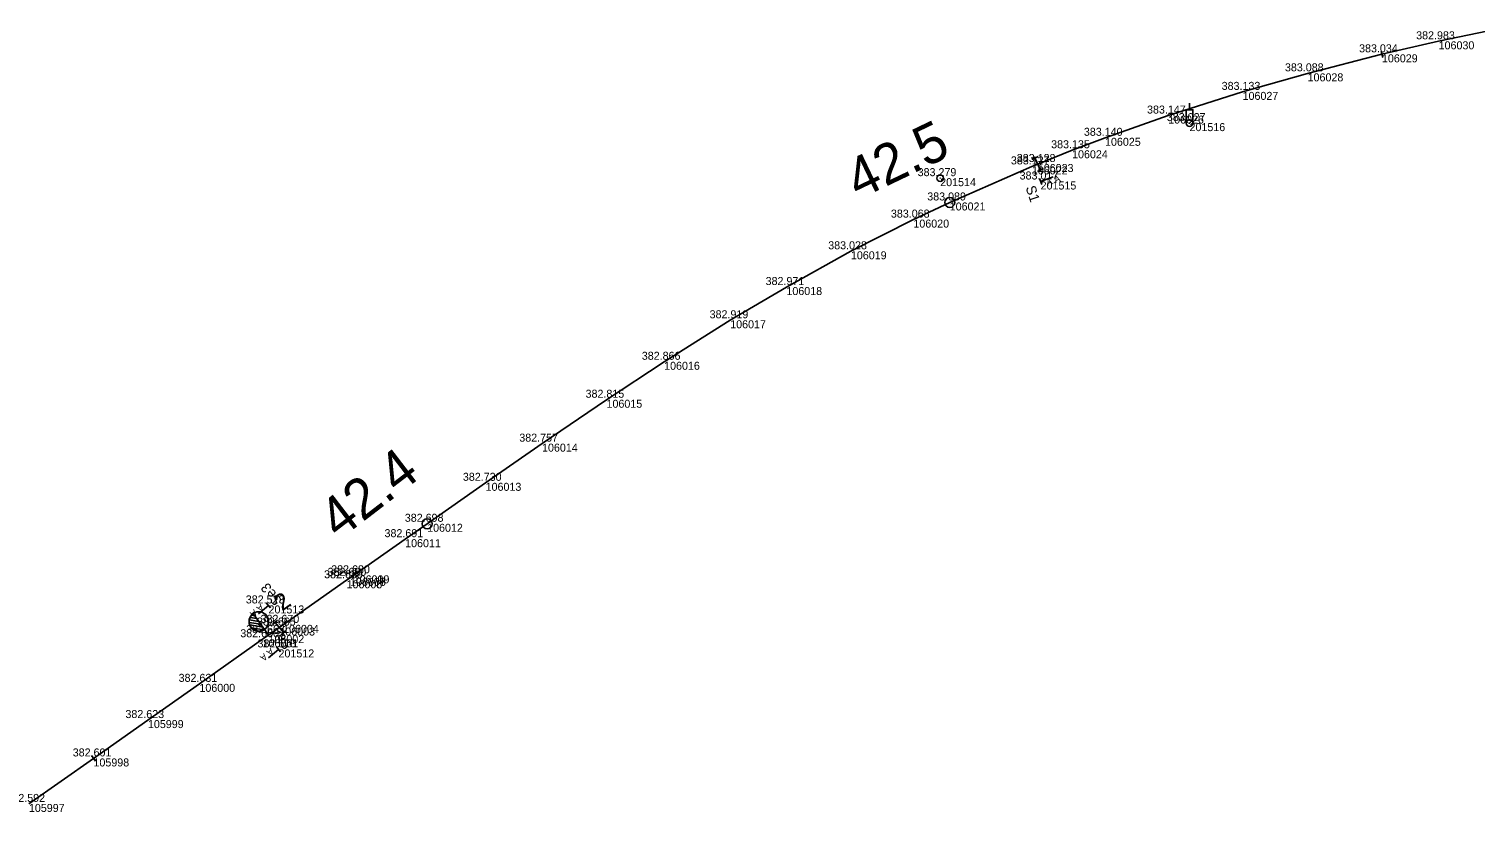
# Model space of a CAD drawing. Extents: x -514522 to -512811, y -1144589 to -1143575.
# Drawn here: x -513451.6 to -513234.8, y -1143710.1 to -1143592.8 of the extents above; entities that cross this region are included whole.
import ezdxf

# ---------------------------------------------------------------- set-up
doc = ezdxf.new("R2010")
doc.units = 0
for name, color, linetype in [('Vrstva 1', 7, 'Continuous'), ('Vrstva 2', 7, 'Continuous'), ('Vrstva 3', 7, 'Continuous'), ('Vrstva 4', 7, 'Continuous'), ('Vrstva 50', 7, 'Continuous'), ('Vrstva 6', 7, 'Continuous'), ('Vrstva 60', 7, 'Continuous'), ('Vrstva 61', 7, 'Continuous'), ('Vrstva 7', 7, 'Continuous')]:
    doc.layers.add(name, color=color, linetype=linetype)

msp = doc.modelspace()

# ---------------------------------------------------------------- linework, layer by layer
at = {"layer": 'Vrstva 1'}
for p, q in [((-513240.22, -1143594.63), (-513231.3, -1143592.78)), ((-513259.87, -1143599.43), (-513248.72, -1143596.58)), ((-513248.72, -1143596.58), (-513240.22, -1143594.63)), ((-513269.62, -1143602.21), (-513259.87, -1143599.43)), ((-513280.78, -1143605.76), (-513269.62, -1143602.21)), ((-513290.25, -1143609.09), (-513280.78, -1143605.76)), ((-513295.19, -1143610.96), (-513290.25, -1143609.09)), ((-513300.33, -1143613.02), (-513295.19, -1143610.96)), ((-513313.54, -1143618.78), (-513301.22, -1143613.38)), ((-513301.22, -1143613.38), (-513300.33, -1143613.02)), ((-513318.99, -1143621.35), (-513313.54, -1143618.78)), ((-513328.36, -1143626.1), (-513318.99, -1143621.35)), ((-513338.03, -1143631.46), (-513328.36, -1143626.1)), ((-513346.46, -1143636.44), (-513338.03, -1143631.46)), ((-513356.37, -1143642.66), (-513346.46, -1143636.44)), ((-513365.01, -1143648.35), (-513356.37, -1143642.66)), ((-513374.68, -1143654.93), (-513365.01, -1143648.35)), ((-513383.14, -1143660.8), (-513374.68, -1143654.93)), ((-513391.91, -1143666.94), (-513383.14, -1143660.8)), ((-513395.21, -1143669.25), (-513391.91, -1143666.94)), ((-513402.93, -1143674.67), (-513395.21, -1143669.25)), ((-513403.47, -1143675.04), (-513402.93, -1143674.67)), ((-513413.51, -1143682.09), (-513404, -1143675.41)), ((-513404, -1143675.41), (-513403.47, -1143675.04)), ((-513415.7, -1143683.62), (-513414.08, -1143682.49)), ((-513414.08, -1143682.49), (-513413.51, -1143682.09)), ((-513426.06, -1143690.93), (-513416.59, -1143684.25)), ((-513416.59, -1143684.25), (-513415.7, -1143683.62)), ((-513433.78, -1143696.36), (-513426.06, -1143690.93)), ((-513441.95, -1143702.11), (-513433.78, -1143696.36)), ((-513451.63, -1143708.93), (-513441.95, -1143702.11))]:
    msp.add_line(p, q, dxfattribs=at)
at = {"layer": 'Vrstva 2'}
for p, q in [((-513248.61, -1143597.07), (-513248.84, -1143596.1)), ((-513417.47, -1143681.15), (-513418.47, -1143680.98)), ((-513417.78, -1143680.72), (-513418.25, -1143680.64)), ((-513416.3, -1143682.79), (-513418, -1143680.41)), ((-513418, -1143680.41), (-513416.3, -1143682.79)), ((-513416.85, -1143682.01), (-513418.6, -1143681.72)), ((-513417.16, -1143681.58), (-513418.59, -1143681.34)), ((-513416.54, -1143682.44), (-513418.51, -1143682.11)), ((-513416.39, -1143682.84), (-513418.27, -1143682.54)), ((-513416.3, -1143682.79), (-513415.7, -1143683.62)), ((-513416.3, -1143682.79), (-513416.3, -1143682.79)), ((-513441.67, -1143702.53), (-513442.23, -1143701.69))]:
    msp.add_line(p, q, dxfattribs=at)
msp.add_circle((-513417.15, -1143681.59), 1.46, dxfattribs=at)
msp.add_arc((-513417.15, -1143681.6), 1.46, 125.6292, 305.5901, dxfattribs=at)
at = {"layer": 'Vrstva 3'}
for p, q in [((-513301.21, -1143612.33), (-513300.3, -1143611.9)), ((-513300.76, -1143612.11), (-513299.91, -1143613.93)), ((-513300.36, -1143614.14), (-513299.46, -1143613.71)), ((-513415.11, -1143682.04), (-513414.34, -1143681.4)), ((-513414.72, -1143681.72), (-513413.44, -1143683.25)), ((-513413.82, -1143683.57), (-513413.05, -1143682.93))]:
    msp.add_line(p, q, dxfattribs=at)
at = {"layer": 'Vrstva 4'}
msp.add_line((-513295.19, -1143610.96), (-513290.25, -1143609.09), dxfattribs=at)
at = {"layer": 'Vrstva 50'}
for p, q in [((-513277.58, -1143603.89), (-513277.58, -1143604.89)), ((-513277.53, -1143606.89), (-513277.63, -1143606.89))]:
    msp.add_line(p, q, dxfattribs=at)
msp.add_lwpolyline([(-513278.09, -1143606.89), (-513278.08, -1143604.89), (-513277.07, -1143604.89), (-513277.07, -1143606.89)], dxfattribs=at)
msp.add_circle((-513277.58, -1143606.89), 0.506, dxfattribs=at)
at = {"layer": 'Vrstva 6'}
for p, q in [((-513300.08, -1143615.17), (-513299.74, -1143616.11)), ((-513298.05, -1143614.96), (-513299.91, -1143615.64)), ((-513415.38, -1143679.56), (-513416.03, -1143678.8)), ((-513417.22, -1143680.45), (-513415.7, -1143679.18)), ((-513413.88, -1143686.15), (-513414.52, -1143685.38)), ((-513415.72, -1143687.04), (-513414.2, -1143685.77))]:
    msp.add_line(p, q, dxfattribs=at)
at = {"layer": 'Vrstva 60'}
for p, q in [((-513248.72, -1143596.58), (-513248.72, -1143596.58)), ((-513240.22, -1143594.63), (-513240.22, -1143594.63)), ((-513259.87, -1143599.43), (-513259.87, -1143599.43)), ((-513269.62, -1143602.21), (-513269.62, -1143602.21)), ((-513280.78, -1143605.76), (-513280.78, -1143605.76)), ((-513277.58, -1143606.89), (-513277.58, -1143606.89)), ((-513290.25, -1143609.09), (-513290.25, -1143609.09)), ((-513295.19, -1143610.96), (-513295.19, -1143610.96)), ((-513301.22, -1143613.38), (-513301.22, -1143613.38)), ((-513300.33, -1143613.02), (-513300.33, -1143613.02)), ((-513314.97, -1143615.14), (-513314.97, -1143615.14)), ((-513299.91, -1143615.64), (-513299.91, -1143615.64)), ((-513313.54, -1143618.78), (-513313.54, -1143618.78)), ((-513318.99, -1143621.35), (-513318.99, -1143621.35)), ((-513328.36, -1143626.1), (-513328.36, -1143626.1)), ((-513338.03, -1143631.46), (-513338.03, -1143631.46)), ((-513346.46, -1143636.44), (-513346.46, -1143636.44)), ((-513356.37, -1143642.66), (-513356.37, -1143642.66)), ((-513365.01, -1143648.35), (-513365.01, -1143648.35)), ((-513374.68, -1143654.93), (-513374.68, -1143654.93)), ((-513383.14, -1143660.8), (-513383.14, -1143660.8)), ((-513391.91, -1143666.94), (-513391.91, -1143666.94)), ((-513395.21, -1143669.25), (-513395.21, -1143669.25)), ((-513402.93, -1143674.66), (-513402.93, -1143674.66)), ((-513402.93, -1143674.67), (-513402.93, -1143674.67)), ((-513404, -1143675.41), (-513404, -1143675.41)), ((-513403.99, -1143675.41), (-513403.99, -1143675.41)), ((-513403.47, -1143675.04), (-513403.47, -1143675.04)), ((-513403.47, -1143675.04), (-513403.47, -1143675.04)), ((-513415.7, -1143679.18), (-513415.7, -1143679.18)), ((-513414.08, -1143682.49), (-513414.08, -1143682.49)), ((-513413.51, -1143682.09), (-513413.51, -1143682.09)), ((-513416.59, -1143684.25), (-513416.59, -1143684.25)), ((-513415.7, -1143683.62), (-513415.7, -1143683.62)), ((-513414.2, -1143685.77), (-513414.2, -1143685.77)), ((-513426.06, -1143690.93), (-513426.06, -1143690.93)), ((-513433.78, -1143696.36), (-513433.78, -1143696.36)), ((-513441.95, -1143702.11), (-513441.95, -1143702.11)), ((-513451.63, -1143708.93), (-513451.63, -1143708.93))]:
    msp.add_line(p, q, dxfattribs=at)
at = {"layer": 'Vrstva 7'}
msp.add_line((-513315.02, -1143615.14), (-513314.92, -1143615.14), dxfattribs=at)
for centre, radius in [((-513314.97, -1143615.14), 0.5), ((-513313.54, -1143618.78), 0.75), ((-513391.91, -1143666.94), 0.75)]:
    msp.add_circle(centre, radius, dxfattribs=at)

# ---------------------------------------------------------------- texts
at = {"layer": 'Vrstva 2'}
msp.add_text('2', height=2.5, rotation=35.5807, dxfattribs=at).set_placement((-513413.65, -1143680.12))
at = {"layer": 'Vrstva 6'}
for s, height, rotation, p in [('  A A ', 1, 20, (-513299.57, -1143616.58)), ('S1', 1.5, 288.4684, (-513302.18, -1143616.55)), ('Se3', 1.5, 128.4684, (-513413.59, -1143678.46)), ('  A A ', 1, 220, (-513416.35, -1143678.41)), ('Se4', 1.5, 128.4684, (-513412.09, -1143685.05)), ('  A A ', 1, 220, (-513414.85, -1143685))]:
    msp.add_text(s, height=height, rotation=rotation, dxfattribs=at).set_placement(p)
at = {"layer": 'Vrstva 60'}
for s, p in [('106029', (-513248.72, -1143597.78)), ('106030', (-513240.22, -1143595.83)), ('106028', (-513259.87, -1143600.63)), ('106027', (-513269.62, -1143603.41)), ('106026', (-513280.78, -1143606.96)), ('201516', (-513277.58, -1143608.09)), ('106025', (-513290.25, -1143610.29)), ('106024', (-513295.19, -1143612.16)), ('106022', (-513301.22, -1143614.58)), ('106023', (-513300.33, -1143614.22)), ('201514', (-513314.97, -1143616.34)), ('201515', (-513299.91, -1143616.84)), ('106021', (-513313.54, -1143619.98)), ('106020', (-513318.99, -1143622.55)), ('106019', (-513328.36, -1143627.3)), ('106018', (-513338.03, -1143632.66)), ('106017', (-513346.46, -1143637.64)), ('106016', (-513356.37, -1143643.86)), ('106015', (-513365.01, -1143649.55)), ('106014', (-513374.68, -1143656.13)), ('106013', (-513383.14, -1143662)), ('106012', (-513391.91, -1143668.14)), ('106011', (-513395.21, -1143670.45)), ('106010', (-513402.93, -1143675.86)), ('106009', (-513402.93, -1143675.87)), ('106006', (-513403.99, -1143676.61)), ('106005', (-513404, -1143676.61)), ('106008', (-513403.47, -1143676.24)), ('106007', (-513403.47, -1143676.24)), ('201513', (-513415.7, -1143680.38)), ('106003', (-513414.08, -1143683.69)), ('106004', (-513413.51, -1143683.29)), ('106001', (-513416.59, -1143685.45)), ('106002', (-513415.7, -1143684.82)), ('201512', (-513414.2, -1143686.97)), ('106000', (-513426.06, -1143692.13)), ('105999', (-513433.78, -1143697.56)), ('105998', (-513441.95, -1143703.31)), ('105997', (-513451.63, -1143710.13))]:
    msp.add_text(s, height=1.2, dxfattribs=at).set_placement(p)
at = {"layer": 'Vrstva 61'}
for s, p in [('382.983', (-513243.59, -1143594.33)), ('383.034', (-513252.15, -1143596.28)), ('383.088', (-513263.27, -1143599.13)), ('383.133', (-513272.76, -1143601.91)), ('383.147', (-513283.95, -1143605.46)), ('383.027', (-513280.98, -1143606.59)), ('383.135', (-513298.33, -1143610.66)), ('383.140', (-513293.42, -1143608.79)), ('383.128', (-513303.48, -1143612.72)), ('383.279', (-513318.35, -1143614.84)), ('383.127', (-513304.37, -1143613.08)), ('383.017', (-513303.06, -1143615.34)), ('383.089', (-513316.91, -1143618.48)), ('383.068', (-513322.36, -1143621.05)), ('383.028', (-513331.76, -1143625.8)), ('382.971', (-513341.15, -1143631.16)), ('382.919', (-513349.55, -1143636.14)), ('382.866', (-513359.72, -1143642.36)), ('382.815', (-513368.15, -1143648.05)), ('382.757', (-513378.09, -1143654.63)), ('382.730', (-513386.55, -1143660.5)), ('382.698', (-513395.26, -1143666.64)), ('382.691', (-513398.3, -1143668.95)), ('382.680', (-513407.37, -1143675.11)), ('382.679', (-513407.35, -1143675.11)), ('382.680', (-513406.84, -1143674.74)), ('382.680', (-513406.84, -1143674.74)), ('382.680', (-513406.3, -1143674.36)), ('382.680', (-513406.3, -1143674.37)), ('382.523', (-513419.11, -1143678.88)), ('382.665', (-513417.43, -1143682.19)), ('382.670', (-513416.89, -1143681.79)), ('382.660', (-513419.93, -1143683.95)), ('382.663', (-513419.05, -1143683.32)), ('382.513', (-513417.35, -1143685.47)), ('382.631', (-513429.18, -1143690.63)), ('382.623', (-513437.16, -1143696.06)), ('382.601', (-513445.06, -1143701.81)), ('382.592', (-513455.01, -1143708.63))]:
    msp.add_text(s, height=1.2, dxfattribs=at).set_placement(p)
at = {"layer": 'Vrstva 7'}
for s, rotation, p in [('42.5', 25.5884, (-513327.23, -1143618.4)), ('42.4', 37.535, (-513405.14, -1143669.45))]:
    msp.add_text(s, height=6, rotation=rotation, dxfattribs=at).set_placement(p)

doc.saveas('drawing.dxf')
